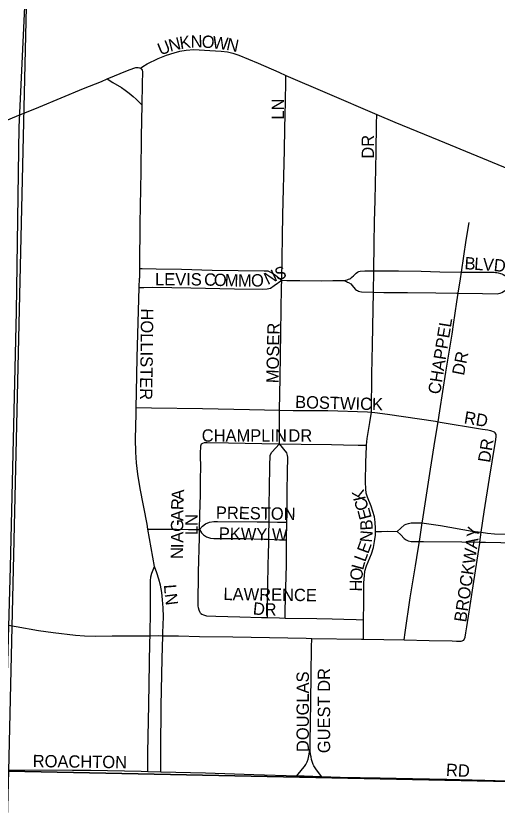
# Model space of a CAD drawing. Extents: x -5.6 to 34, y 0 to 22.
# Drawn here: x 3.152 to 3.932, y 16.786 to 18.084 of the extents above; entities that cross this region are included whole.
import ezdxf

# ---------------------------------------------------------------- set-up
doc = ezdxf.new("R2010")
doc.units = 0
for name, color, linetype in [('GM_X_City_Street', 7, 'Continuous'), ('GM_X_City_Street_Text', 7, 'Continuous'), ('GM_X_Minor_River', 7, 'Continuous'), ('GM_X_Section', 7, 'Continuous')]:
    doc.layers.add(name, color=color, linetype=linetype)

msp = doc.modelspace()

# ---------------------------------------------------------------- linework, layer by layer
at = {"layer": 'GM_X_City_Street'}
for points in [[(3.3534, 17.9991), (3.3573, 18.0016), (3.3642, 18.006), (3.3821, 18.0146), (3.3961, 18.0202), (3.4083, 18.0242), (3.4174, 18.0267), (3.4279, 18.0284), (3.4403, 18.0292), (3.4662, 18.0279), (3.4844, 18.0269), (3.4947, 18.0256), (3.5034, 18.0235), (3.5132, 18.0203), (3.5446, 18.0072), (3.5783, 17.9925), (3.5898, 17.9875)], [(3.2997, 17.9816), (3.3325, 17.9953), (3.3427, 17.9994), (3.3462, 18.0003), (3.3497, 18.0004), (3.3518, 17.9999), (3.3534, 17.9991)], [(3.3534, 17.9991), (3.3537, 17.999), (3.3552, 17.9976), (3.3563, 17.9959), (3.3567, 17.994), (3.3566, 17.9732), (3.3558, 17.9398)], [(3.1116, 17.9045), (3.1524, 17.9211), (3.1885, 17.936), (3.2609, 17.966), (3.2901, 17.9776), (3.2997, 17.9816)], [(3.2997, 17.9816), (3.3089, 17.976), (3.3226, 17.9676), (3.3287, 17.9637), (3.3352, 17.9586), (3.3417, 17.9534), (3.3466, 17.949), (3.3527, 17.9429), (3.3558, 17.9398)], [(3.5829, 17.655), (3.5846, 17.761), (3.5874, 17.8661), (3.5881, 17.9015), (3.5889, 17.9449), (3.5896, 17.9777), (3.5898, 17.9875)], [(3.5898, 17.9875), (3.6566, 17.9586), (3.7371, 17.9242)], [(3.3558, 17.9398), (3.3552, 17.9142), (3.3545, 17.8879), (3.3541, 17.8314), (3.3526, 17.7474), (3.3521, 17.6787), (3.352, 17.674)], [(3.7322, 17.6706), (3.7328, 17.7143), (3.7336, 17.7498), (3.7346, 17.7852), (3.7359, 17.8627), (3.7368, 17.9086), (3.7371, 17.9242)], [(3.7371, 17.9242), (3.7665, 17.9116), (3.8381, 17.8821), (3.9522, 17.8353), (4.0001, 17.8167)], [(3.8748, 17.6684), (3.8824, 17.72), (3.8871, 17.7485)], [(3.352, 17.674), (3.3519, 17.6582)], [(3.352, 17.674), (3.3566, 17.6739), (3.3792, 17.6737), (3.4202, 17.6728), (3.4702, 17.6717), (3.5545, 17.6706), (3.5602, 17.6701), (3.5633, 17.6689), (3.5678, 17.6667), (3.5734, 17.663), (3.5829, 17.655)], [(3.6837, 17.6546), (3.6891, 17.6558), (3.6914, 17.6566), (3.6934, 17.6574), (3.6953, 17.6585), (3.6969, 17.66), (3.6995, 17.6624), (3.7039, 17.6668), (3.7056, 17.668), (3.7068, 17.6687), (3.7083, 17.6693), (3.7102, 17.6698), (3.7177, 17.6706), (3.7294, 17.6706), (3.7322, 17.6706)], [(3.7317, 17.6357), (3.7322, 17.6706)], [(3.7322, 17.6706), (3.7726, 17.6705), (3.8093, 17.6699), (3.8395, 17.669), (3.8748, 17.6684)], [(3.8695, 17.6341), (3.8732, 17.6575), (3.8748, 17.6684)], [(3.8748, 17.6684), (3.875, 17.6684), (3.9208, 17.6683), (3.9275, 17.668), (3.93, 17.6679), (3.9321, 17.6675), (3.9343, 17.6671), (3.9382, 17.6661), (3.9402, 17.6654), (3.9423, 17.6642), (3.945, 17.6627), (3.9471, 17.6617), (3.9489, 17.6609), (3.9508, 17.6604), (3.953, 17.66), (3.957, 17.6597), (3.9591, 17.6597), (3.9623, 17.6597), (3.9717, 17.6597), (3.9801, 17.6598)], [(3.3515, 17.6433), (3.3519, 17.6582)], [(3.3515, 17.6433), (3.3592, 17.6434), (3.3737, 17.6437), (3.4353, 17.6426), (3.506, 17.6411), (3.5517, 17.6406), (3.559, 17.6409), (3.5644, 17.6424), (3.5706, 17.6463), (3.5829, 17.655)], [(3.5794, 17.4444), (3.5806, 17.4968), (3.5827, 17.644), (3.5829, 17.655)], [(3.5829, 17.655), (3.5913, 17.6549), (3.6122, 17.6547), (3.6475, 17.6544), (3.6658, 17.6545), (3.6837, 17.6546)], [(3.6837, 17.6546), (3.6879, 17.6532), (3.6899, 17.6522), (3.6913, 17.6515), (3.6948, 17.649), (3.6995, 17.644), (3.7028, 17.6402), (3.7043, 17.639), (3.7056, 17.6383), (3.7077, 17.6374), (3.7098, 17.6369), (3.7123, 17.6365), (3.7317, 17.6357)], [(3.3468, 17.4485), (3.3473, 17.4732), (3.3484, 17.5296), (3.3515, 17.6433)], [(3.8695, 17.6341), (3.909, 17.6334), (3.9324, 17.6331), (3.9347, 17.6334), (3.9377, 17.6342), (3.9402, 17.6353), (3.9446, 17.6378), (3.9488, 17.6403), (3.9513, 17.6417), (3.9545, 17.6428), (3.9586, 17.6437), (3.9732, 17.6446), (3.9781, 17.6446)], [(3.7287, 17.441), (3.7294, 17.5029), (3.7304, 17.5502), (3.7313, 17.6079), (3.7317, 17.6357)], [(3.7317, 17.6357), (3.7317, 17.6357), (3.7487, 17.6354), (3.787, 17.6353), (3.8329, 17.6344), (3.867, 17.6341), (3.8695, 17.6341)], [(3.8367, 17.4255), (3.8396, 17.4433), (3.8491, 17.5057), (3.8593, 17.5676), (3.8618, 17.5835), (3.8672, 17.62), (3.8695, 17.6341)], [(3.3658, 17.2515), (3.3645, 17.2593), (3.3532, 17.3172), (3.3493, 17.3406), (3.3471, 17.3589), (3.346, 17.376), (3.3457, 17.3971), (3.3466, 17.4391), (3.3468, 17.4485)], [(3.3468, 17.4485), (3.3715, 17.4482), (3.4542, 17.447), (3.5303, 17.4453), (3.5794, 17.4444)], [(3.5793, 17.3897), (3.5794, 17.3982), (3.5794, 17.4263), (3.5794, 17.4343), (3.5794, 17.4444)], [(3.5794, 17.4444), (3.6012, 17.444), (3.6576, 17.4435), (3.722, 17.4415), (3.7287, 17.441)], [(3.7206, 17.3873), (3.7217, 17.3984), (3.7246, 17.418), (3.7258, 17.4245), (3.7287, 17.441)], [(3.7287, 17.441), (3.7338, 17.4406), (3.7547, 17.4378), (3.8067, 17.4301), (3.8326, 17.4262), (3.8367, 17.4255)], [(3.811, 17.2615), (3.8114, 17.2642), (3.8245, 17.3486), (3.8321, 17.3966), (3.8367, 17.4255)], [(3.8367, 17.4255), (3.909, 17.4137), (3.9173, 17.4123), (3.9217, 17.4112), (3.9275, 17.409), (3.9294, 17.4073)], [(3.9067, 17.2462), (3.9115, 17.2796), (3.92, 17.3342), (3.9289, 17.3869), (3.9302, 17.3963), (3.9308, 17.4021), (3.9308, 17.4048), (3.9294, 17.4073)], [(3.4528, 17.3896), (3.455, 17.3907), (3.4573, 17.3916), (3.4599, 17.392), (3.4621, 17.392), (3.4963, 17.3915), (3.5779, 17.3898), (3.5793, 17.3897)], [(3.4494, 17.2505), (3.4499, 17.2747), (3.4509, 17.3075), (3.4511, 17.3295), (3.4513, 17.3545), (3.4511, 17.368), (3.4511, 17.3764), (3.4513, 17.3836), (3.4518, 17.3867), (3.4528, 17.3896)], [(3.5625, 17.2629), (3.5627, 17.2757), (3.5625, 17.2908), (3.563, 17.3178), (3.5633, 17.3536), (3.5642, 17.3714), (3.5668, 17.3759), (3.5793, 17.3897)], [(3.5793, 17.3897), (3.6147, 17.389), (3.6634, 17.3884), (3.6832, 17.388), (3.7068, 17.3876), (3.7206, 17.3873)], [(3.5914, 17.2625), (3.5917, 17.2757), (3.5916, 17.3124), (3.5925, 17.3438), (3.5928, 17.3678), (3.5924, 17.371), (3.5913, 17.375), (3.5793, 17.3897)], [(3.735, 17.2475), (3.7351, 17.2521), (3.7345, 17.2624), (3.7332, 17.2713), (3.731, 17.28), (3.728, 17.2886), (3.7221, 17.3033), (3.7202, 17.3098), (3.7192, 17.3166), (3.7189, 17.3273), (3.7196, 17.3602), (3.7204, 17.3852), (3.7206, 17.3873)], [(3.4494, 17.2505), (3.4541, 17.2562), (3.4591, 17.26), (3.4657, 17.2628), (3.4729, 17.2638), (3.4784, 17.2637), (3.5431, 17.2632), (3.5625, 17.2629)], [(3.5618, 17.2349), (3.562, 17.2481), (3.5624, 17.2585), (3.5625, 17.2629)], [(3.5625, 17.2629), (3.576, 17.2627), (3.5914, 17.2625)], [(3.5908, 17.2338), (3.5914, 17.2625)], [(3.3762, 17.1908), (3.3658, 17.2515)], [(3.3658, 17.2515), (3.3772, 17.2515), (3.3859, 17.2515), (3.4123, 17.2511), (3.4317, 17.2508), (3.4431, 17.2506), (3.4494, 17.2505)], [(3.451, 17.1147), (3.4498, 17.1173), (3.449, 17.1199), (3.448, 17.1238), (3.4475, 17.1266), (3.4471, 17.1328), (3.4473, 17.1462), (3.4476, 17.1643), (3.448, 17.1814), (3.4492, 17.2379), (3.4494, 17.2505)], [(3.4494, 17.2505), (3.4529, 17.2453), (3.456, 17.2421), (3.461, 17.2387), (3.467, 17.2368), (3.4726, 17.2362), (3.4821, 17.2362), (3.4901, 17.2363), (3.5215, 17.2361), (3.5542, 17.2352), (3.5618, 17.2349)], [(3.7701, 17.2477), (3.7824, 17.2581), (3.7847, 17.2594), (3.7884, 17.2606), (3.7929, 17.2615), (3.7984, 17.2615), (3.811, 17.2615)], [(3.8064, 17.2311), (3.811, 17.2615)], [(3.811, 17.2615), (3.8139, 17.2611), (3.8404, 17.2571), (3.8921, 17.2482), (3.9067, 17.2462)], [(3.7157, 17.1043), (3.7159, 17.1313), (3.7164, 17.1642), (3.717, 17.1762), (3.718, 17.1829), (3.7207, 17.192), (3.7286, 17.2114), (3.7317, 17.2213), (3.7337, 17.2314), (3.7349, 17.2417), (3.735, 17.2475)], [(3.735, 17.2475), (3.7397, 17.2475), (3.745, 17.2476), (3.7544, 17.2479), (3.7701, 17.2477)], [(3.7701, 17.2477), (3.776, 17.2419), (3.7815, 17.2361), (3.7846, 17.2337), (3.7881, 17.2321), (3.7929, 17.231), (3.8064, 17.2311)], [(3.9044, 17.2302), (3.9067, 17.2462)], [(3.9067, 17.2462), (3.9168, 17.2448), (3.9285, 17.2438), (3.9573, 17.2429), (3.9888, 17.2429), (4.026, 17.2431), (4.0315, 17.2438), (4.0365, 17.2449), (4.0409, 17.2464), (4.0446, 17.2476)], [(3.5596, 17.1077), (3.5596, 17.1152), (3.5596, 17.133), (3.5608, 17.1913), (3.5615, 17.213), (3.5617, 17.2273), (3.5618, 17.2349)], [(3.5618, 17.2349), (3.579, 17.2342), (3.5908, 17.2338)], [(3.5884, 17.1071), (3.5887, 17.1198), (3.5904, 17.1931), (3.5905, 17.1997), (3.5906, 17.2187), (3.5908, 17.2324), (3.5908, 17.2338)], [(3.7815, 17.0715), (3.7833, 17.0837), (3.7916, 17.1397), (3.7998, 17.1916), (3.8045, 17.2187), (3.8064, 17.2311)], [(3.8064, 17.2311), (3.8132, 17.2311), (3.8754, 17.2309), (3.9044, 17.2302)], [(3.8785, 17.0711), (3.8805, 17.0761), (3.8818, 17.0832), (3.8835, 17.0929), (3.8887, 17.1274), (3.8947, 17.1664), (3.9042, 17.2288), (3.9044, 17.2302)], [(3.9044, 17.2302), (3.9135, 17.23), (3.9634, 17.2292), (4.0028, 17.2284), (4.0119, 17.2275), (4.0188, 17.2257), (4.025, 17.2225), (4.0288, 17.2194), (4.0311, 17.2174), (4.0347, 17.2131), (4.0381, 17.2069)], [(3.3691, 17.0783), (3.3697, 17.1203), (3.3701, 17.1672), (3.3705, 17.1737), (3.372, 17.1798), (3.3762, 17.1908)], [(3.3899, 17.0784), (3.3901, 17.0831), (3.391, 17.1092), (3.3905, 17.1236), (3.3895, 17.1365), (3.3882, 17.1483), (3.386, 17.1603), (3.3834, 17.1703), (3.3804, 17.1806), (3.3762, 17.1908)], [(2.9744, 17.111), (2.9777, 17.1111), (3.0105, 17.1112), (3.0367, 17.1104), (3.0562, 17.109), (3.0717, 17.1065), (3.0782, 17.1057), (3.1093, 17.1011), (3.152, 17.0933), (3.1883, 17.0871), (3.2117, 17.0836), (3.2483, 17.0793), (3.2628, 17.0783), (3.2812, 17.0779), (3.3076, 17.0782), (3.3128, 17.0781), (3.3234, 17.0782), (3.3533, 17.078), (3.3691, 17.0783)], [(3.451, 17.1147), (3.4532, 17.1131), (3.4558, 17.1121), (3.4576, 17.1115), (3.4608, 17.1108), (3.4759, 17.1099), (3.5147, 17.1089), (3.55, 17.1079), (3.5596, 17.1077)], [(3.5596, 17.1077), (3.5791, 17.1073), (3.5884, 17.1071)], [(3.5884, 17.1071), (3.6401, 17.1064), (3.6647, 17.1058), (3.6837, 17.1052), (3.7036, 17.1046), (3.7157, 17.1043)], [(3.7154, 17.0726), (3.7156, 17.0919), (3.7157, 17.1043)], [(3.3653, 16.8582), (3.3655, 16.8738), (3.3656, 16.8883), (3.3671, 16.9669), (3.369, 17.0679), (3.3691, 17.0783)], [(3.3691, 17.0783), (3.3826, 17.0785), (3.3899, 17.0784)], [(3.3866, 16.8576), (3.3866, 16.8729), (3.3866, 16.8846), (3.3864, 16.8926), (3.387, 16.9648), (3.3886, 17.041), (3.3899, 17.0784)], [(3.3899, 17.0784), (3.4152, 17.0782), (3.4494, 17.0773), (3.5033, 17.0764), (3.6228, 17.0742), (3.6316, 17.0741)], [(3.6288, 16.8966), (3.6288, 16.9053), (3.63, 16.9708), (3.6309, 17.0153), (3.6314, 17.0598), (3.6316, 17.0741)], [(3.6316, 17.0741), (3.7121, 17.0727), (3.7154, 17.0726)], [(3.7154, 17.0726), (3.7815, 17.0715)], [(3.7815, 17.0715), (3.8224, 17.0707), (3.8598, 17.0699), (3.8664, 17.0697), (3.8741, 17.0697), (3.8785, 17.0711)], [(3.6075, 16.8512), (3.6165, 16.8623), (3.6197, 16.8662), (3.6218, 16.8692), (3.6243, 16.8738), (3.6257, 16.8783), (3.6269, 16.8836), (3.6288, 16.8966)], [(3.6475, 16.8499), (3.6383, 16.8624), (3.6369, 16.8643), (3.6351, 16.8674), (3.6341, 16.8696), (3.6329, 16.8726), (3.6314, 16.8777), (3.6305, 16.8821), (3.6298, 16.8859), (3.6292, 16.8914), (3.6288, 16.8966)], [(3.1051, 16.8615), (3.1386, 16.8609), (3.2435, 16.8604), (3.2729, 16.86), (3.3546, 16.8585), (3.3653, 16.8582)], [(3.3653, 16.8582), (3.3866, 16.8576)], [(3.3866, 16.8576), (3.4593, 16.8557), (3.5377, 16.8534), (3.6075, 16.8512)], [(3.6075, 16.8512), (3.6195, 16.8508), (3.6475, 16.8499)], [(3.6475, 16.8499), (3.6775, 16.849), (3.7428, 16.8476), (3.7952, 16.8468), (3.8507, 16.8457), (3.9128, 16.8441), (3.9808, 16.8421)]]:
    msp.add_lwpolyline(points, dxfattribs=at)
at = {"layer": 'GM_X_Minor_River'}
msp.add_lwpolyline([(3.1727, 18.2606), (3.156, 17.9033), (3.1519, 17.6042), (3.1419, 17.1897), (3.1336, 16.8819), (3.1308, 16.8323), (3.1221, 16.5076), (3.1169, 16.2286), (3.1032, 15.8929), (3.0921, 15.5667), (3.0838, 15.1603), (3.0776, 14.8396), (3.0715, 14.6841), (2.7803, 14.6952), (2.5171, 14.7048), (2.3034, 14.7157)], dxfattribs=at)
at = {"layer": 'GM_X_Section'}
for points in [[(2.1, 19.0324), (2.1, 16.9188), (3.1401, 16.8587), (3.1889, 18.9888), (2.7758, 19.0054), (2.2725, 19.0255)], [(3.1889, 18.9888), (5.3166, 18.9352), (5.2895, 16.8144), (3.1401, 16.8587)], [(3.1401, 16.8587), (5.2895, 16.8144), (5.2575, 14.6921), (3.0791, 14.7168)]]:
    msp.add_lwpolyline(points, close=True, dxfattribs=at)

# ---------------------------------------------------------------- texts
at = {"layer": 'GM_X_City_Street_Text'}
for s, rotation, p in [('U', 22.0246, (3.3863, 18.0194)), ('N', 13.9302, (3.4019, 18.0258)), ('K', 8.5567, (3.4185, 18.03)), ('N', 1.0273, (3.4352, 18.0325)), ('O', 355.3834, (3.4523, 18.0328)), ('W', 353.5818, (3.4697, 18.0314)), ('N', 348.18, (3.4919, 18.029)), ('LN', 90, (3.5865, 17.9157)), ('DR', 90, (3.7326, 17.8523)), ('B', 356.4524, (3.8791, 17.673)), ('L', 356.4762, (3.8949, 17.672)), ('V', 356.4564, (3.9089, 17.6712)), ('S', 17.5969, (3.5752, 17.6544)), ('D', 354.1546, (3.9263, 17.6701)), ('LEVIS', 0, (3.3773, 17.6466)), ('C', 357.9841, (3.4566, 17.6466)), ('O', 357.9671, (3.4724, 17.6461)), ('M', 358.5629, (3.4902, 17.6454)), ('M', 0.0001, (3.5119, 17.6449)), ('O', 0.1729, (3.5331, 17.6449)), ('N', 25.4168, (3.56, 17.6471)), ('HOLLISTER', 269.2466, (3.3546, 17.6094)), ('CHAPPEL', 80.8385, (3.8399, 17.4691)), ('MOSER', 88.8298, (3.5777, 17.4879)), ('DR', 78.6859, (3.8786, 17.4996)), ('BOSTWICK', 358.4497, (3.6044, 17.4478)), ('RD', 350.5416, (3.8777, 17.4231)), ('CHAMPLIN', 0, (3.453, 17.3932)), ('DR', 0, (3.5937, 17.3932)), ('DR', 81.0215, (3.9209, 17.3583)), ('A', 87.5076, (3.4238, 17.2977)), ('K', 102.8062, (3.7196, 17.2997)), ('C', 110.3377, (3.725, 17.2855)), ('R', 87.5948, (3.4231, 17.2818)), ('PRESTON', 359.0599, (3.4759, 17.2682)), ('A', 89.7562, (3.423, 17.2644)), ('E', 104.6719, (3.7292, 17.2698)), ('G', 89.7562, (3.423, 17.2468)), ('LN', 90, (3.4463, 17.2416)), ('B', 93.4972, (3.7308, 17.2498)), ('PKWY W', 358.9823, (3.4806, 17.2342)), ('BROCKWAY', 81.5722, (3.8822, 17.0994)), ('A', 89.7562, (3.4229, 17.2292)), ('N', 85.0715, (3.7293, 17.2291)), ('I', 89.7556, (3.4229, 17.2204)), ('E', 69.8628, (3.7232, 17.2102)), ('N', 89.7595, (3.4228, 17.2028)), ('L', 70.1219, (3.7184, 17.197)), ('L', 74.6514, (3.7148, 17.1838)), ('O', 84.9223, (3.7134, 17.1672)), ('L', 274.5391, (3.3916, 17.1609)), ('H', 89.2786, (3.7132, 17.15)), ('N', 277.0641, (3.3928, 17.1459)), ('LAWRENCE', 359.256, (3.4882, 17.1362)), ('D', 354.0436, (3.5354, 17.1131)), ('R', 359.5721, (3.555, 17.1111)), ('DOUGLAS', 90, (3.6269, 16.8896)), ('GUEST DR', 90, (3.6614, 16.8878)), ('ROACHTON', 359.255, (3.1786, 16.8652)), ('RD', 356.989, (3.8491, 16.8511))]:
    msp.add_text(s, height=0.02, rotation=rotation, dxfattribs=at).set_placement(p)

doc.saveas('drawing.dxf')
